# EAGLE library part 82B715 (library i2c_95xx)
I²C Bus Extender
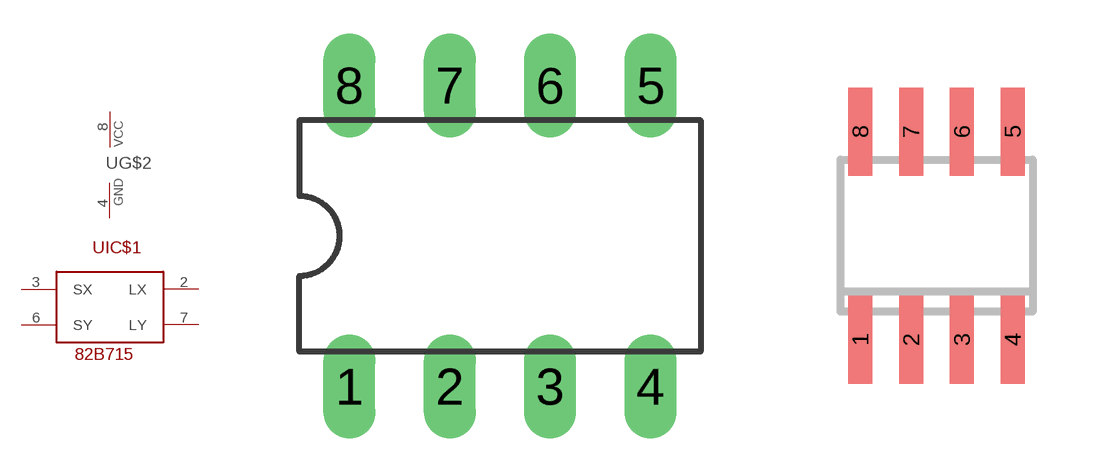
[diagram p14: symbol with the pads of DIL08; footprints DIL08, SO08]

Designator prefix -; gates IC$1=82B715 G$2=PWRN

## 82B715PN  [DIL08]
2  IC$1:LX
3  IC$1:SX
4  G$2:GND  pwr
6  IC$1:SY
7  IC$1:LY
8  G$2:VCC  pwr

## 82B715TD  [SO08]
Pads as for DIL08

## Footprint DIL08 (pad centres in mm)
drill 0.813 long: 1 -3.81,-3.81; 2 -1.27,-3.81; 3 1.27,-3.81; 4 3.81,-3.81; 5 3.81,3.81; 6 1.27,3.81; 7 -1.27,3.81; 8 -3.81,3.81

## Footprint SO08 (pad centres in mm)
smd 0.6 x 2.2: 1 -1.905,-2.6; 2 -0.635,-2.6; 3 0.635,-2.6; 4 1.905,-2.6; 5 1.905,2.6; 6 0.635,2.6; 7 -0.635,2.6; 8 -1.905,2.6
